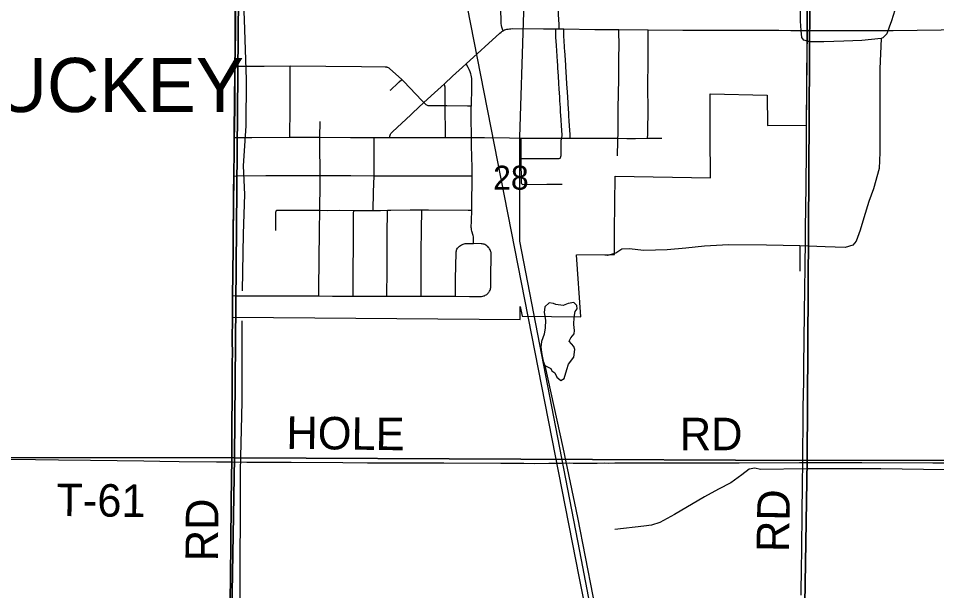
# Model space of a CAD drawing. Extents: x -8.3 to 42.1, y 0 to 22.
# Drawn here: x 3.551 to 5.158, y 19.103 to 20.104 of the extents above; entities that cross this region are included whole.
import ezdxf

# ---------------------------------------------------------------- set-up
doc = ezdxf.new("R2010")
doc.units = 0
for name, color, linetype in [('GM_X_City_Street', 7, 'Continuous'), ('GM_X_Corporation', 7, 'Continuous'), ('GM_X_Corporation_Text', 7, 'Continuous'), ('GM_X_County_Road', 7, 'Continuous'), ('GM_X_County_Road_Text', 7, 'Continuous'), ('GM_X_Minor_Lake', 7, 'Continuous'), ('GM_X_Minor_River', 7, 'Continuous'), ('GM_X_Rail_Line', 7, 'Continuous'), ('GM_X_Section', 7, 'Continuous'), ('GM_X_Section_Text', 7, 'Continuous'), ('GM_X_State_Route', 7, 'Continuous'), ('GM_X_Township_Road', 7, 'Continuous'), ('GM_X_Township_Road_Text', 7, 'Continuous')]:
    doc.layers.add(name, color=color, linetype=linetype)

msp = doc.modelspace()

# ---------------------------------------------------------------- linework, layer by layer
at = {"layer": 'GM_X_City_Street'}
for points in [[(4.3991, 20.0825), (4.3981, 20.0851), (4.3975, 20.0868), (4.3969, 20.0889), (4.3962, 20.0914), (4.3957, 20.0952), (4.3956, 20.099), (4.3953, 20.1195), (4.3955, 20.1354), (4.3957, 20.1746), (4.3975, 20.2477), (4.3982, 20.2862), (4.3987, 20.3263), (4.3989, 20.3382)], [(4.4976, 20.0858), (4.4972, 20.0935), (4.4964, 20.1108), (4.4942, 20.1548), (4.4933, 20.174), (4.4916, 20.2056), (4.491, 20.2161), (4.49, 20.2335), (4.4896, 20.2403), (4.4891, 20.2502), (4.4875, 20.2806), (4.4871, 20.2892), (4.4858, 20.3115), (4.4853, 20.3274), (4.4849, 20.3379)], [(4.5019, 19.8945), (4.5025, 19.9), (4.502, 19.9082), (4.5015, 19.9161), (4.5009, 19.9268), (4.4999, 19.941), (4.4995, 19.9479), (4.4987, 19.9597), (4.4983, 19.9665), (4.4974, 19.9807), (4.4968, 19.99), (4.496, 20.0037), (4.4952, 20.0167), (4.4947, 20.0222), (4.4943, 20.0288), (4.4925, 20.0568), (4.4917, 20.0711), (4.4915, 20.0802), (4.4915, 20.0858)], [(4.5167, 19.8943), (4.5163, 19.901), (4.5154, 19.9162), (4.5148, 19.9248), (4.5144, 19.9328), (4.5142, 19.9365), (4.5141, 19.9384), (4.5141, 19.9408), (4.5139, 19.9433), (4.513, 19.9569), (4.5118, 19.9748), (4.5113, 19.9828), (4.5108, 19.9889), (4.5101, 20.0012), (4.509, 20.0192), (4.5088, 20.0222), (4.5083, 20.0308), (4.5071, 20.0481), (4.5069, 20.0517), (4.5068, 20.054), (4.5067, 20.0551), (4.5056, 20.0734), (4.5054, 20.0786), (4.5054, 20.0804), (4.5055, 20.0858)], [(4.5993, 19.8638), (4.5996, 19.8726), (4.5998, 19.8807), (4.6001, 19.8944), (4.6003, 19.8999), (4.6008, 19.9471), (4.6017, 19.9979), (4.6018, 20.0311), (4.6021, 20.061), (4.602, 20.0777), (4.6019, 20.0844)], [(4.6518, 19.8944), (4.6523, 19.9007), (4.6526, 19.9088), (4.6528, 19.9409), (4.6526, 19.9867), (4.653, 20.0274), (4.653, 20.0452), (4.6528, 20.0752), (4.6528, 20.0839)], [(3.93, 20.0205), (3.9401, 20.0206), (3.9812, 20.0207), (4.0269, 20.0209), (4.1513, 20.0197), (4.1931, 20.0195), (4.194, 20.0194), (4.1949, 20.0192), (4.1957, 20.019), (4.1968, 20.0185)], [(4.026, 19.896), (4.0261, 19.9028), (4.0264, 19.9413), (4.0267, 19.9943), (4.0269, 20.0209)], [(4.3475, 19.7103), (4.3475, 19.7192), (4.3472, 19.7218), (4.3468, 19.7239), (4.3446, 19.7319), (4.3441, 19.7339), (4.3438, 19.7361), (4.3435, 19.7379), (4.3438, 19.7496), (4.3443, 19.7682), (4.3445, 19.777), (4.3451, 19.8254), (4.345, 19.8287), (4.3449, 19.8401), (4.3448, 19.8486), (4.3445, 19.8564), (4.3443, 19.8631), (4.344, 19.8803), (4.3439, 19.8954), (4.3439, 19.9025), (4.3435, 19.9248), (4.3436, 19.9487), (4.3437, 19.9512), (4.344, 19.9618), (4.3445, 19.973), (4.3446, 19.9872), (4.3446, 19.9957), (4.3443, 19.9987), (4.3439, 20.0016), (4.3433, 20.0046), (4.3427, 20.0073), (4.3416, 20.0107), (4.3401, 20.0145), (4.3383, 20.0182), (4.3345, 20.0248)], [(4.2603, 19.9567), (4.2569, 19.9605), (4.2254, 19.9937), (4.2218, 19.9971), (4.2162, 20.0025), (4.2012, 20.0156), (4.1998, 20.0168), (4.1988, 20.0175), (4.1978, 20.0181), (4.1968, 20.0185)], [(4.2017, 19.9783), (4.2026, 19.9792), (4.2148, 19.9907), (4.2175, 19.9931), (4.2218, 19.9971)], [(4.298, 19.9514), (4.2979, 19.9687), (4.2978, 19.982), (4.2977, 19.984), (4.2975, 19.9853), (4.2969, 19.9897)], [(4.2603, 19.9567), (4.2642, 19.9532), (4.2652, 19.9526), (4.2664, 19.9521), (4.2676, 19.9518), (4.2691, 19.9517), (4.2711, 19.9516), (4.298, 19.9514), (4.3008, 19.9514), (4.3367, 19.9512), (4.3437, 19.9512)], [(4.2985, 19.8954), (4.2983, 19.9161), (4.2981, 19.9346), (4.298, 19.9441), (4.298, 19.9514)], [(4.077, 19.6184), (4.077, 19.6305), (4.0777, 19.7323), (4.0783, 19.7682), (4.0789, 19.8145), (4.0789, 19.8291), (4.079, 19.8389), (4.0788, 19.8772), (4.0787, 19.896), (4.0789, 19.9238)], [(4.172, 19.7681), (4.1727, 19.7999), (4.1735, 19.8286), (4.1737, 19.8579), (4.1736, 19.8881), (4.1736, 19.8957)], [(4.2002, 19.8957), (4.2393, 19.8956), (4.2734, 19.8955), (4.2985, 19.8954), (4.3106, 19.8954), (4.3298, 19.8954), (4.3439, 19.8954), (4.3665, 19.8955), (4.4103, 19.895), (4.4311, 19.8947), (4.4785, 19.8942), (4.5019, 19.8945), (4.5167, 19.8943), (4.5325, 19.8943), (4.566, 19.8944), (4.6001, 19.8944), (4.6157, 19.894), (4.6306, 19.8941), (4.6518, 19.8944), (4.6615, 19.8945), (4.6769, 19.8947)], [(4.432, 19.8143), (4.4313, 19.8153), (4.4311, 19.8588), (4.4311, 19.8872), (4.4311, 19.8947)], [(4.4311, 19.8588), (4.4338, 19.8588), (4.4558, 19.8587), (4.4965, 19.8586), (4.4975, 19.8589), (4.4982, 19.8592), (4.4989, 19.8597), (4.4994, 19.8601), (4.4999, 19.8609), (4.5002, 19.8617), (4.5004, 19.8626), (4.5006, 19.8644), (4.5008, 19.8887), (4.501, 19.891), (4.5019, 19.8945)], [(3.9282, 19.8282), (3.9343, 19.8288), (3.9839, 19.8289), (4.0331, 19.829), (4.0789, 19.8291), (4.133, 19.8292), (4.1735, 19.8286), (4.1926, 19.8283), (4.2989, 19.8285), (4.3362, 19.8287), (4.345, 19.8287)], [(4.432, 19.8143), (4.4328, 19.8137), (4.4338, 19.8134), (4.476, 19.8139), (4.5028, 19.8142)], [(4.0016, 19.7329), (4.0015, 19.7648), (4.0016, 19.7656), (4.0019, 19.7663), (4.0024, 19.7674)], [(4.0024, 19.7674), (4.0029, 19.7679), (4.0035, 19.7684), (4.0041, 19.7685), (4.0048, 19.7686), (4.0447, 19.7684), (4.068, 19.7683), (4.0783, 19.7682), (4.0912, 19.7679), (4.1125, 19.7682), (4.1379, 19.7681), (4.1596, 19.768), (4.172, 19.7681), (4.1845, 19.7681), (4.1972, 19.7682), (4.203, 19.7682), (4.2368, 19.7688), (4.2569, 19.769), (4.2686, 19.7691), (4.338, 19.7683), (4.3443, 19.7682)], [(4.1366, 19.618), (4.1367, 19.6229), (4.1371, 19.6651), (4.1372, 19.7054), (4.1377, 19.7628), (4.1379, 19.7681)], [(4.196, 19.6181), (4.196, 19.6249), (4.1962, 19.6562), (4.1966, 19.6993), (4.1966, 19.7344), (4.1971, 19.7584), (4.1972, 19.7682)], [(4.2556, 19.618), (4.2557, 19.625), (4.2559, 19.6526), (4.2559, 19.6896), (4.2566, 19.7398), (4.2568, 19.7625), (4.2569, 19.769)], [(4.316, 19.6177), (4.3161, 19.6246), (4.3162, 19.6484), (4.317, 19.6938), (4.3171, 19.6957), (4.3174, 19.6971), (4.3178, 19.6986), (4.3185, 19.7002), (4.3195, 19.7017), (4.3205, 19.703), (4.3219, 19.7045), (4.3232, 19.7057), (4.3247, 19.7069), (4.3263, 19.7078), (4.3279, 19.7086), (4.3294, 19.7091), (4.3312, 19.7096), (4.3328, 19.71), (4.3348, 19.7102), (4.3475, 19.7103)], [(4.3717, 19.622), (4.3728, 19.6232), (4.3739, 19.6244), (4.3748, 19.6256), (4.3756, 19.6268), (4.3763, 19.6282), (4.3769, 19.6298), (4.3773, 19.6313), (4.3777, 19.633), (4.3779, 19.6349), (4.3776, 19.6486), (4.3783, 19.6925), (4.3782, 19.6942), (4.3778, 19.6958), (4.3771, 19.6975), (4.3763, 19.6991), (4.3756, 19.7005), (4.3746, 19.7021), (4.3737, 19.7034), (4.3725, 19.7046), (4.3713, 19.7057), (4.3702, 19.7065), (4.3689, 19.7074), (4.3675, 19.7081), (4.3661, 19.7088), (4.3645, 19.7092), (4.3628, 19.7096), (4.3611, 19.7097), (4.3475, 19.7103)], [(3.9262, 19.619), (3.9331, 19.6188), (3.9436, 19.6186), (3.9932, 19.6184), (4.0181, 19.6183), (4.0653, 19.6184), (4.077, 19.6184), (4.1007, 19.6181), (4.1343, 19.618), (4.1366, 19.618), (4.1603, 19.618), (4.1861, 19.6181), (4.196, 19.6181), (4.2315, 19.6179), (4.2556, 19.618), (4.2872, 19.618), (4.316, 19.6177), (4.3406, 19.6174), (4.3613, 19.6176), (4.3635, 19.6178), (4.3653, 19.6183), (4.3667, 19.6187), (4.368, 19.6194), (4.3693, 19.6202), (4.3705, 19.621), (4.3717, 19.622)]]:
    msp.add_lwpolyline(points, dxfattribs=at)
at = {"layer": 'GM_X_Corporation'}
msp.add_lwpolyline([(3.9317, 20.2038), (3.9305, 20.0825), (3.9297, 20.0211), (3.9295, 19.9525), (3.9286, 19.8963), (3.928, 19.8287), (3.926, 19.6196), (3.9258, 19.5809), (4.4292, 19.5769), (4.429, 19.5839), (4.4291, 19.5998), (4.4323, 19.5829), (4.5351, 19.5816), (4.5278, 19.6903), (4.5943, 19.6906), (4.5943, 19.7321), (4.5952, 19.828), (4.7623, 19.8251), (4.7613, 19.8991), (4.7616, 19.9721), (4.8612, 19.9698), (4.8618, 19.9167), (4.93, 19.9172), (4.9305, 19.9698), (4.9315, 20.0835), (4.932, 20.3341)], dxfattribs=at)
at = {"layer": 'GM_X_County_Road'}
for points in [[(3.93, 20.0205), (3.93, 20.0235), (3.9303, 20.0471), (3.9307, 20.082), (3.9309, 20.1224), (3.9313, 20.1572), (3.9319, 20.2032), (3.9325, 20.2598), (3.9327, 20.2946), (3.9331, 20.3201), (3.9336, 20.3437)], [(3.9289, 19.8957), (3.929, 19.9134), (3.9297, 19.952), (3.9297, 19.9657), (3.93, 20.0042), (3.93, 20.0205)], [(3.9282, 19.8282), (3.9288, 19.8724), (3.9289, 19.8957)], [(3.9262, 19.619), (3.9265, 19.6549), (3.9269, 19.7053), (3.9271, 19.7299), (3.9278, 19.7741), (3.928, 19.8002), (3.9282, 19.8282)], [(3.926, 19.5814), (3.926, 19.594), (3.9262, 19.619)], [(3.9246, 19.3278), (3.9246, 19.33), (3.9248, 19.3596), (3.9251, 19.3925), (3.9251, 19.4087), (3.9252, 19.4242), (3.9253, 19.4404), (3.9255, 19.4615), (3.9254, 19.4839), (3.9255, 19.5019), (3.9259, 19.5168), (3.9256, 19.5398), (3.926, 19.5804), (3.926, 19.5814)], [(3.9219, 19.0874), (3.9222, 19.1247), (3.9236, 19.252), (3.9243, 19.3017), (3.9246, 19.3278)]]:
    msp.add_lwpolyline(points, dxfattribs=at)
at = {"layer": 'GM_X_Minor_Lake'}
msp.add_line((4.5042, 19.6014), (4.4917, 19.6032), dxfattribs=at)
msp.add_lwpolyline([(4.4917, 19.6032), (4.4876, 19.6052), (4.48, 19.6061), (4.4723, 19.5995), (4.4713, 19.5896), (4.4732, 19.5759), (4.4729, 19.5623), (4.4711, 19.5517), (4.4663, 19.5385), (4.4653, 19.5287), (4.4672, 19.5161), (4.4696, 19.5043), (4.4724, 19.4966), (4.4825, 19.4915), (4.4847, 19.4872), (4.4899, 19.4837), (4.4931, 19.476), (4.5005, 19.4701), (4.5063, 19.4738), (4.5109, 19.4896), (4.5137, 19.4987), (4.5228, 19.5114), (4.525, 19.5246), (4.5232, 19.5299), (4.5147, 19.5392), (4.5179, 19.5452), (4.5234, 19.5523), (4.5239, 19.558), (4.523, 19.5686), (4.5237, 19.5812), (4.5255, 19.591), (4.5286, 19.5958), (4.5284, 19.6015), (4.5232, 19.6066), (4.5133, 19.6049), (4.5042, 19.6014)], dxfattribs=at)
at = {"layer": 'GM_X_Minor_River'}
for points in [[(3.9525, 20.7227), (3.951, 20.6276), (3.9502, 20.535), (3.9503, 20.417), (3.9494, 20.3191), (3.9493, 20.1639), (3.9439, 20.1599), (3.9459, 20.1014), (3.9497, 19.9973), (3.9492, 19.9161), (3.9445, 19.846), (3.9466, 19.7959), (3.9445, 19.7268), (3.9428, 19.6275)], [(5.163, 20.3), (5.15, 20.2791), (5.1383, 20.2649), (5.1272, 20.2466), (5.1214, 20.224), (5.1151, 20.2014), (5.1062, 20.1788), (5.0989, 20.1558), (5.0927, 20.1374), (5.0849, 20.1185), (5.0786, 20.1), (5.0745, 20.0889), (5.0705, 20.0769), (5.0638, 20.0698), (5.0607, 20.0691), (5.0271, 20.0654), (4.9955, 20.0642), (4.9606, 20.0632), (4.936, 20.063), (4.9254, 20.0661), (4.9218, 20.0709), (4.921, 20.0827), (4.9198, 20.0995), (4.9198, 20.1567)], [(5.0607, 20.0691), (5.0586, 20.0156), (5.0582, 19.9371), (5.0584, 19.8695), (5.057, 19.8415), (5.0474, 19.8057), (5.0394, 19.7834), (5.0306, 19.7548), (5.024, 19.7337), (5.0171, 19.7142), (5.0112, 19.7071), (4.9975, 19.7033), (4.9627, 19.7041), (4.9184, 19.7063), (4.8601, 19.707), (4.7935, 19.7078), (4.7514, 19.7054), (4.7187, 19.702), (4.6861, 19.699), (4.6453, 19.6979), (4.6199, 19.7006), (4.607, 19.7002), (4.5966, 19.6932), (4.5821, 19.6894), (4.5772, 19.6899)], [(4.9184, 19.7063), (4.9185, 19.6619)], [(3.937, 19.0125), (3.9394, 19.0758), (3.9399, 19.3122), (3.9425, 19.4328), (3.9426, 19.5747)], [(4.4724, 19.4966), (4.5037, 19.3532), (4.5294, 19.2308), (4.5563, 19.0931), (4.583, 18.9612)], [(5.5787, 19.3184), (5.492, 19.3175), (5.3833, 19.3167), (5.2943, 19.3166), (5.1719, 19.3139), (5.0602, 19.3158), (4.9307, 19.3155), (4.8496, 19.3145), (4.8398, 19.317), (4.8299, 19.3149), (4.8172, 19.3054), (4.7975, 19.2914), (4.7764, 19.2802), (4.7519, 19.2667), (4.6992, 19.2358), (4.6735, 19.222), (4.659, 19.2174), (4.6453, 19.2154), (4.5948, 19.2094)]]:
    msp.add_lwpolyline(points, dxfattribs=at)
at = {"layer": 'GM_X_Rail_Line'}
for points in [[(4.1842, 20.9), (4.2824, 20.3978), (4.5315, 19.127), (4.6541, 18.5101), (4.7015, 18.2399), (4.7193, 18.1628), (4.7437, 18.1035), (4.7782, 18.045), (4.9031, 17.884), (5.1089, 17.6286), (5.1497, 17.5693), (5.1874, 17.5157), (5.2262, 17.4447), (5.2601, 17.3769), (5.294, 17.2671), (5.315, 17.167), (5.3312, 17.0685), (5.3428, 16.9248)], [(4.4602, 20.9), (4.4279, 19.896), (4.4279, 19.7141), (4.5329, 19.1719), (4.7134, 18.2287), (4.7298, 18.1615), (4.7562, 18.1061), (4.7924, 18.0389), (4.852, 17.9646), (5.1115, 17.6457), (5.209, 17.5403), (5.4439, 17.3636), (5.6263, 17.2359), (5.6901, 17.1722)]]:
    msp.add_lwpolyline(points, dxfattribs=at)
at = {"layer": 'GM_X_Section'}
for points in [[(3.938, 20.3445), (3.9295, 19.335), (2.9241, 19.3359), (2.9276, 20.3504)], [(4.9373, 20.3372), (4.9315, 19.3303), (3.9295, 19.335), (3.938, 20.3445)], [(5.9413, 20.342), (5.9346, 19.331), (4.9315, 19.3303), (4.9373, 20.3372)], [(2.9241, 19.3359), (3.9295, 19.335), (3.9115, 18.3241), (3.9047, 18.3241), (2.9164, 18.3298), (2.9226, 18.6969)], [(4.9315, 19.3303), (4.9147, 18.3251), (4.8893, 18.3249), (3.9115, 18.3241), (3.9295, 19.335)], [(5.9346, 19.331), (5.9121, 18.3219), (5.8932, 18.3221), (4.9147, 18.3251), (4.9315, 19.3303)]]:
    msp.add_lwpolyline(points, close=True, dxfattribs=at)
at = {"layer": 'GM_X_State_Route'}
for p, q in [((4.8815, 20.0833), (4.9024, 20.0831)), ((4.9024, 20.0831), (4.9318, 20.083))]:
    msp.add_line(p, q, dxfattribs=at)
for points in [[(3.9336, 20.3437), (3.9331, 20.3201), (3.9327, 20.2946), (3.9325, 20.2598), (3.9319, 20.2032), (3.9313, 20.1572), (3.9309, 20.1224), (3.9307, 20.082), (3.9303, 20.0471), (3.93, 20.0235), (3.93, 20.0205)], [(4.2412, 19.9387), (4.2603, 19.9567), (4.2794, 19.974), (4.2969, 19.9897), (4.3109, 20.0028), (4.3283, 20.0188), (4.3345, 20.0248), (4.3937, 20.0785), (4.3956, 20.0801), (4.397, 20.0812), (4.3991, 20.0825), (4.4002, 20.0831), (4.4018, 20.0838), (4.4038, 20.0845), (4.4058, 20.085), (4.4082, 20.0855), (4.4106, 20.0859), (4.4128, 20.0861), (4.4153, 20.0862), (4.4698, 20.0861), (4.4915, 20.0858), (4.4976, 20.0858), (4.5055, 20.0858), (4.56, 20.0848), (4.6019, 20.0844), (4.6528, 20.0839), (4.7139, 20.0837), (4.8245, 20.0836), (4.8815, 20.0833)], [(4.9318, 20.083), (4.9352, 20.0829), (4.9551, 20.0827), (5.0816, 20.0829), (5.1657, 20.0839), (5.2092, 20.0844), (5.2453, 20.0844), (5.3111, 20.085), (5.3434, 20.0854), (5.3862, 20.0851), (5.4229, 20.0852), (5.4437, 20.0853), (5.5021, 20.0855), (5.5524, 20.0856), (5.6084, 20.0857), (5.6531, 20.0858), (5.77, 20.0858), (5.9402, 20.0853)], [(3.93, 20.0205), (3.93, 20.0042), (3.9297, 19.9657), (3.9297, 19.952), (3.929, 19.9134), (3.9289, 19.8957)], [(4.2056, 19.9054), (4.2376, 19.9352), (4.2412, 19.9387)], [(3.9289, 19.8957), (3.9594, 19.8957), (4.026, 19.896), (4.0278, 19.896), (4.0431, 19.896)], [(4.0431, 19.896), (4.0787, 19.896), (4.1323, 19.8959), (4.1623, 19.8957)], [(4.1623, 19.8957), (4.1736, 19.8957), (4.1834, 19.8956), (4.2002, 19.8957), (4.2014, 19.8999), (4.2021, 19.9015), (4.2027, 19.9025), (4.2034, 19.9034), (4.2056, 19.9054)]]:
    msp.add_lwpolyline(points, dxfattribs=at)
at = {"layer": 'GM_X_Township_Road'}
for points in [[(4.9318, 20.083), (4.9321, 20.1052), (4.9321, 20.1263), (4.9319, 20.1555), (4.9322, 20.284), (4.9327, 20.3339)], [(3.9306, 20.1229), (3.9305, 20.0825), (3.9301, 20.0477), (3.9298, 20.0241), (3.9297, 20.0211), (3.9297, 20.0048), (3.9294, 19.9662), (3.9295, 19.9525), (3.9288, 19.914), (3.9286, 19.8963), (3.9286, 19.8729), (3.928, 19.8287), (3.9277, 19.8008), (3.9276, 19.7746), (3.9269, 19.7305), (3.9267, 19.7059), (3.9263, 19.6555), (3.926, 19.6196), (3.9258, 19.5945), (3.9258, 19.5809), (3.9254, 19.5404), (3.9256, 19.5174), (3.9253, 19.5024), (3.9251, 19.4844), (3.9252, 19.462), (3.9251, 19.4409), (3.925, 19.4248), (3.9248, 19.4092), (3.9248, 19.3931), (3.9245, 19.3602), (3.9244, 19.3306), (3.9244, 19.3284), (3.9241, 19.3023), (3.9234, 19.2526), (3.922, 19.1252), (3.9217, 19.0879)], [(3.9217, 19.0879), (3.922, 19.1252), (3.9234, 19.2526), (3.9241, 19.3023), (3.9244, 19.3284), (3.9244, 19.3306), (3.9245, 19.3602), (3.9248, 19.3931), (3.9248, 19.4092), (3.925, 19.4248), (3.9251, 19.4409), (3.9252, 19.462), (3.9251, 19.4844), (3.9253, 19.5024), (3.9256, 19.5174), (3.9254, 19.5404), (3.9258, 19.5809), (3.9258, 19.5945), (3.926, 19.6196), (3.9263, 19.6555), (3.9267, 19.7059), (3.9269, 19.7305), (3.9276, 19.7746), (3.9277, 19.8008), (3.928, 19.8287), (3.9286, 19.8729), (3.9286, 19.8963), (3.9288, 19.914), (3.9295, 19.9525), (3.9294, 19.9662), (3.9297, 20.0048), (3.9297, 20.0211), (3.9298, 20.0241), (3.9301, 20.0477), (3.9305, 20.0825), (3.9306, 20.1229)], [(4.9303, 19.9167), (4.9309, 19.9893), (4.9311, 20.0191), (4.9314, 20.0332), (4.9315, 20.0499), (4.9316, 20.0685), (4.9318, 20.083)], [(4.9301, 19.9008), (4.9303, 19.9102), (4.9303, 19.9167)], [(4.9236, 19.3267), (4.9239, 19.3437), (4.9244, 19.3965), (4.9245, 19.4239), (4.9252, 19.4686), (4.9255, 19.4991), (4.9261, 19.5389), (4.9267, 19.5902), (4.9278, 19.669), (4.9282, 19.7167), (4.9285, 19.736), (4.9293, 19.8112), (4.93, 19.8734), (4.9301, 19.8945), (4.9301, 19.9008)], [(2.9261, 19.3397), (2.9375, 19.3396), (2.9841, 19.3391), (3.0401, 19.3383), (3.1084, 19.3373), (3.1799, 19.3366), (3.2328, 19.3359), (3.2887, 19.3353), (3.3042, 19.3352), (3.3571, 19.3345), (3.3882, 19.334), (3.3975, 19.3338), (3.4348, 19.3335), (3.528, 19.3324), (3.5808, 19.3318), (3.6213, 19.3314), (3.6772, 19.3307), (3.7704, 19.3296), (3.7984, 19.3292), (3.8326, 19.3287), (3.8978, 19.328), (3.9227, 19.3278), (3.9246, 19.3278)], [(3.9246, 19.3278), (3.9507, 19.3276), (3.9786, 19.3274), (4.0284, 19.3274), (4.1185, 19.3268), (4.162, 19.3264), (4.1838, 19.3262), (4.2521, 19.3264), (4.2957, 19.3263), (4.3951, 19.3256), (4.4293, 19.3254), (4.4355, 19.3254), (4.454, 19.3252), (4.479, 19.3256), (4.4989, 19.3257)], [(4.4989, 19.3257), (4.5028, 19.3257), (4.5158, 19.326), (4.5218, 19.3259), (4.5278, 19.3258), (4.5382, 19.3257), (4.5487, 19.3259), (4.5548, 19.3257), (4.5637, 19.3259), (4.5762, 19.326), (4.5828, 19.3259), (4.5948, 19.3262), (4.6476, 19.3261), (4.7067, 19.3265), (4.7658, 19.3265), (4.8124, 19.3264), (4.9181, 19.3267), (4.9236, 19.3267)], [(4.9206, 19.0944), (4.9208, 19.1112), (4.9211, 19.129), (4.9218, 19.1851), (4.9223, 19.2293), (4.9232, 19.2964), (4.9235, 19.3201), (4.9236, 19.3267)], [(4.9236, 19.3267), (4.9492, 19.3268), (5.0269, 19.3269), (5.1512, 19.3265), (5.2134, 19.3261), (5.3004, 19.3259), (5.4558, 19.3268), (5.5024, 19.3272), (5.5242, 19.327), (5.5398, 19.3267), (5.5553, 19.3261), (5.5615, 19.3258), (5.5832, 19.3252), (5.5987, 19.3249), (5.6484, 19.3246), (5.6919, 19.3247), (5.7603, 19.3252), (5.8318, 19.3254), (5.8722, 19.3254), (5.9126, 19.3256), (5.9308, 19.3255)]]:
    msp.add_lwpolyline(points, dxfattribs=at)

# ---------------------------------------------------------------- texts
at = {"layer": 'GM_X_Corporation_Text'}
msp.add_text('LUCKEY', height=0.0947, rotation=0, dxfattribs=at).set_placement((3.4392, 19.9402))
at = {"layer": 'GM_X_County_Road_Text'}
msp.add_text('RD', height=0.05682, rotation=89.5045, dxfattribs=at).set_placement((3.9002, 19.1537))
at = {"layer": 'GM_X_Section_Text'}
msp.add_text('28', height=0.04186, rotation=0, dxfattribs=at).set_placement((4.3817, 19.8044))
at = {"layer": 'GM_X_Township_Road_Text'}
for s, rotation, p in [('HOLE', 359.2621, (4.0197, 19.3508)), ('RD', 0, (4.7084, 19.3483)), ('T-61', 359.2931, (3.6172, 19.2332)), ('RD', 89.0287, (4.8994, 19.1696))]:
    msp.add_text(s, height=0.05682, rotation=rotation, dxfattribs=at).set_placement(p)

doc.saveas('drawing.dxf')
